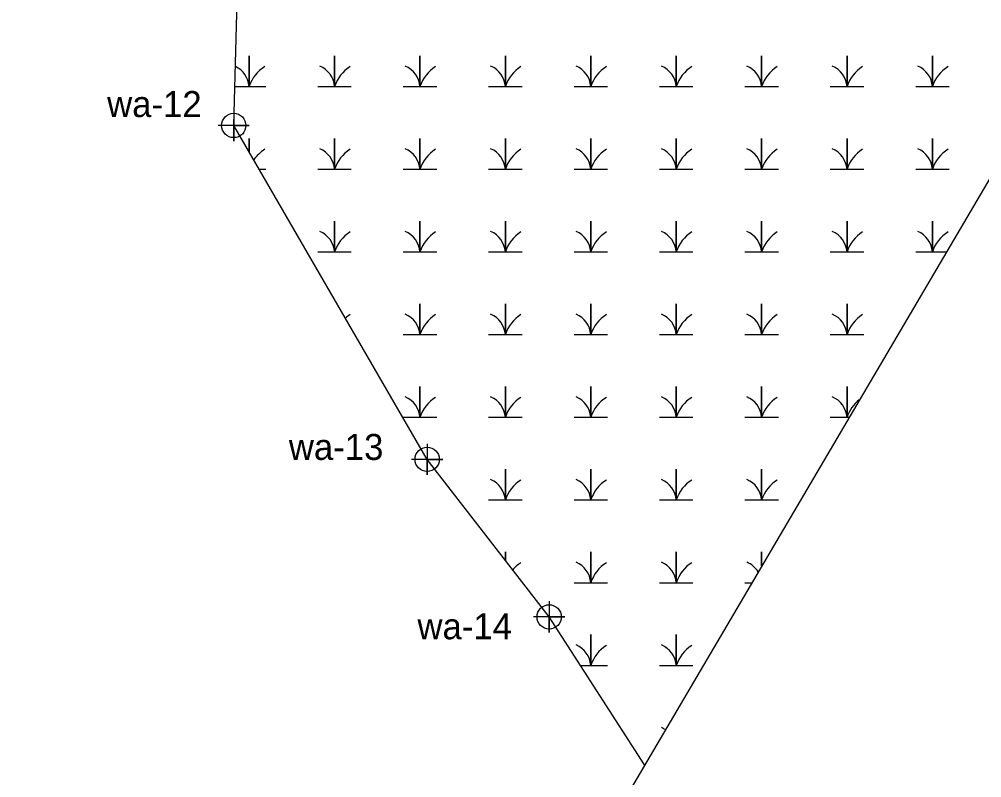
# Model space of a CAD drawing. Extents: x 2379288 to 2381905, y 330670 to 333511.
# Drawn here: x 2379849.1 to 2380034.5, y 331240.1 to 331386.1 of the extents above; entities that cross this region are included whole.
import ezdxf

# ---------------------------------------------------------------- set-up
doc = ezdxf.new("R2010")
doc.units = 0
for name, color, linetype in [('Default', 7, 'Continuous'), ('Exist Environmental Wetland Boundary', 7, 'Continuous'), ('Exist Environmental Wetland Boundary Cogo Number', 7, 'Continuous'), ('Exist Environmental Wetland Boundary Cogo Point CELL', 7, 'Continuous'), ('Exist Hydro Swamp or Marsh', 7, 'Continuous')]:
    doc.layers.add(name, color=color, linetype=linetype)

msp = doc.modelspace()

# ---------------------------------------------------------------- linework, layer by layer
at = {"layer": 'Default'}
msp.add_lwpolyline([(2380453.94, 332065.55), (2379632.78, 330670.47), (2379288.07, 330873.37), (2380109.3, 332268.58)], dxfattribs=at)
at = {"layer": 'Exist Environmental Wetland Boundary'}
msp.add_lwpolyline([(2379969.53, 331242.58), (2379951.18, 331271.07), (2379927.68, 331301.39), (2379890.44, 331365.66), (2379892.64, 331447.19), (2379906.39, 331470.26), (2379921.41, 331493.05), (2379928.27, 331503.45), (2379949.79, 331537.93), (2379979.44, 331586.24), (2380001.81, 331628.04), (2380020.7, 331661.36), (2380049.79, 331711.02), (2380074.34, 331755.11), (2380080.4, 331764.13), (2380105.64, 331802.62), (2380125.36, 331845.41), (2380131.51, 331853.8), (2380135.55, 331859.31), (2380151.44, 331880.98), (2380179.52, 331921.73), (2380190.43, 331937.74), (2380215.91, 331979.8)], dxfattribs=at)
at = {"layer": 'Exist Environmental Wetland Boundary Cogo Point CELL'}
for points in [[(2379890.43, 331368.66), (2379890.43, 331362.66), (2379890.43, 331365.66), (2379893.43, 331365.66), (2379887.43, 331365.66)], [(2379927.68, 331304.39), (2379927.68, 331298.39), (2379927.68, 331301.39), (2379930.68, 331301.39), (2379924.68, 331301.39)], [(2379951.18, 331274.07), (2379951.18, 331268.07), (2379951.18, 331271.07), (2379954.18, 331271.07), (2379948.18, 331271.07)]]:
    msp.add_lwpolyline(points, dxfattribs=at)
for centre in [(2379890.43, 331365.66), (2379927.68, 331301.39), (2379951.18, 331271.07)]:
    msp.add_circle(centre, 2.34, dxfattribs=at)
at = {"layer": 'Exist Hydro Swamp or Marsh'}
for p, q in [((2379895.32, 331357.24), (2379896.62, 331357.24)), ((2379988.87, 331277.65), (2379990.18, 331277.65))]:
    msp.add_line(p, q, dxfattribs=at)
for points in [[(2379890.64, 331373.16), (2379893.39, 331373.16), (2379893.39, 331379.08), (2379893.39, 331373.16), (2379896.62, 331373.16)], [(2379906.62, 331373.16), (2379909.84, 331373.16), (2379909.84, 331379.08), (2379909.84, 331373.16), (2379913.07, 331373.16)], [(2379923.07, 331373.16), (2379926.29, 331373.16), (2379926.29, 331379.08), (2379926.29, 331373.16), (2379929.52, 331373.16)], [(2379939.52, 331373.16), (2379942.75, 331373.16), (2379942.75, 331379.08), (2379942.75, 331373.16), (2379945.97, 331373.16)], [(2379955.97, 331373.16), (2379959.2, 331373.16), (2379959.2, 331379.08), (2379959.2, 331373.16), (2379962.42, 331373.16)], [(2379972.42, 331373.16), (2379975.65, 331373.16), (2379975.65, 331379.08), (2379975.65, 331373.16), (2379978.87, 331373.16)], [(2379988.87, 331373.16), (2379992.1, 331373.16), (2379992.1, 331379.08), (2379992.1, 331373.16), (2379995.32, 331373.16)], [(2380005.32, 331373.16), (2380008.55, 331373.16), (2380008.55, 331379.08), (2380008.55, 331373.16), (2380011.78, 331373.16)], [(2380021.78, 331373.16), (2380025, 331373.16), (2380025, 331379.08), (2380025, 331373.16), (2380028.23, 331373.16)], [(2379893.39, 331360.56), (2379893.39, 331363.16), (2379893.39, 331360.56)], [(2379906.62, 331357.24), (2379909.84, 331357.24), (2379909.84, 331363.16), (2379909.84, 331357.24), (2379913.07, 331357.24)], [(2379923.07, 331357.24), (2379926.29, 331357.24), (2379926.29, 331363.16), (2379926.29, 331357.24), (2379929.52, 331357.24)], [(2379939.52, 331357.24), (2379942.75, 331357.24), (2379942.75, 331363.16), (2379942.75, 331357.24), (2379945.97, 331357.24)], [(2379955.97, 331357.24), (2379959.2, 331357.24), (2379959.2, 331363.16), (2379959.2, 331357.24), (2379962.42, 331357.24)], [(2379972.42, 331357.24), (2379975.65, 331357.24), (2379975.65, 331363.16), (2379975.65, 331357.24), (2379978.87, 331357.24)], [(2379988.87, 331357.24), (2379992.1, 331357.24), (2379992.1, 331363.16), (2379992.1, 331357.24), (2379995.32, 331357.24)], [(2380005.32, 331357.24), (2380008.55, 331357.24), (2380008.55, 331363.16), (2380008.55, 331357.24), (2380011.78, 331357.24)], [(2380021.78, 331357.24), (2380025, 331357.24), (2380025, 331363.16), (2380025, 331357.24), (2380028.23, 331357.24)], [(2379906.62, 331341.33), (2379909.84, 331341.33), (2379909.84, 331347.24), (2379909.84, 331341.33), (2379913.07, 331341.33)], [(2379923.07, 331341.33), (2379926.29, 331341.33), (2379926.29, 331347.24), (2379926.29, 331341.33), (2379929.52, 331341.33)], [(2379939.52, 331341.33), (2379942.75, 331341.33), (2379942.75, 331347.24), (2379942.75, 331341.33), (2379945.97, 331341.33)], [(2379955.97, 331341.33), (2379959.2, 331341.33), (2379959.2, 331347.24), (2379959.2, 331341.33), (2379962.42, 331341.33)], [(2379972.42, 331341.33), (2379975.65, 331341.33), (2379975.65, 331347.24), (2379975.65, 331341.33), (2379978.87, 331341.33)], [(2379988.87, 331341.33), (2379992.1, 331341.33), (2379992.1, 331347.24), (2379992.1, 331341.33), (2379995.32, 331341.33)], [(2380005.32, 331341.33), (2380008.55, 331341.33), (2380008.55, 331347.24), (2380008.55, 331341.33), (2380011.78, 331341.33)], [(2380021.78, 331341.33), (2380025, 331341.33), (2380025, 331347.24), (2380025, 331341.33), (2380027.66, 331341.33)], [(2379923.07, 331325.41), (2379926.29, 331325.41), (2379926.29, 331331.33), (2379926.29, 331325.41), (2379929.52, 331325.41)], [(2379939.52, 331325.41), (2379942.75, 331325.41), (2379942.75, 331331.33), (2379942.75, 331325.41), (2379945.97, 331325.41)], [(2379955.97, 331325.41), (2379959.2, 331325.41), (2379959.2, 331331.33), (2379959.2, 331325.41), (2379962.42, 331325.41)], [(2379972.42, 331325.41), (2379975.65, 331325.41), (2379975.65, 331331.33), (2379975.65, 331325.41), (2379978.87, 331325.41)], [(2379988.87, 331325.41), (2379992.1, 331325.41), (2379992.1, 331331.33), (2379992.1, 331325.41), (2379995.32, 331325.41)], [(2380005.32, 331325.41), (2380008.55, 331325.41), (2380008.55, 331331.33), (2380008.55, 331325.41), (2380011.78, 331325.41)], [(2379923.07, 331309.49), (2379926.29, 331309.49), (2379926.29, 331315.41), (2379926.29, 331309.49), (2379929.52, 331309.49)], [(2379939.52, 331309.49), (2379942.75, 331309.49), (2379942.75, 331315.41), (2379942.75, 331309.49), (2379945.97, 331309.49)], [(2379955.97, 331309.49), (2379959.2, 331309.49), (2379959.2, 331315.41), (2379959.2, 331309.49), (2379962.42, 331309.49)], [(2379972.42, 331309.49), (2379975.65, 331309.49), (2379975.65, 331315.41), (2379975.65, 331309.49), (2379978.87, 331309.49)], [(2379988.87, 331309.49), (2379992.1, 331309.49), (2379992.1, 331315.41), (2379992.1, 331309.49), (2379995.32, 331309.49)], [(2380005.32, 331309.49), (2380008.55, 331309.49), (2380008.55, 331315.41), (2380008.55, 331309.49), (2380008.92, 331309.49)], [(2379939.52, 331293.57), (2379942.75, 331293.57), (2379942.75, 331299.49), (2379942.75, 331293.57), (2379945.97, 331293.57)], [(2379955.97, 331293.57), (2379959.2, 331293.57), (2379959.2, 331299.49), (2379959.2, 331293.57), (2379962.42, 331293.57)], [(2379972.42, 331293.57), (2379975.65, 331293.57), (2379975.65, 331299.49), (2379975.65, 331293.57), (2379978.87, 331293.57)], [(2379988.87, 331293.57), (2379992.1, 331293.57), (2379992.1, 331299.49), (2379992.1, 331293.57), (2379995.32, 331293.57)], [(2379942.75, 331281.95), (2379942.75, 331283.57), (2379942.75, 331281.95)], [(2379955.97, 331277.65), (2379959.2, 331277.65), (2379959.2, 331283.57), (2379959.2, 331277.65), (2379962.42, 331277.65)], [(2379972.42, 331277.65), (2379975.65, 331277.65), (2379975.65, 331283.57), (2379975.65, 331277.65), (2379978.87, 331277.65)], [(2379992.1, 331280.92), (2379992.1, 331283.57), (2379992.1, 331280.92)], [(2379957.19, 331261.74), (2379959.2, 331261.74), (2379959.2, 331267.65), (2379959.2, 331261.74), (2379962.42, 331261.74)], [(2379972.42, 331261.74), (2379975.65, 331261.74), (2379975.65, 331267.65), (2379975.65, 331261.74), (2379978.87, 331261.74)]]:
    msp.add_lwpolyline(points, dxfattribs=at)
for centre, radius, start, end in [((2379888.79, 331372.83), 4.61, 4.1403, 64.9754), ((2379900.23, 331370.89), 7.21, 122.1274, 161.6222), ((2379905.24, 331372.83), 4.61, 4.1403, 67.535), ((2379916.68, 331370.89), 7.21, 122.1274, 161.6222), ((2379921.69, 331372.83), 4.61, 4.1403, 67.535), ((2379933.14, 331370.89), 7.21, 122.1274, 161.6222), ((2379938.15, 331372.83), 4.61, 4.1403, 67.535), ((2379949.59, 331370.89), 7.21, 122.1274, 161.6222), ((2379954.6, 331372.83), 4.61, 4.1403, 67.535), ((2379966.04, 331370.89), 7.21, 122.1274, 161.6222), ((2379971.05, 331372.83), 4.61, 4.1403, 67.535), ((2379982.49, 331370.89), 7.21, 122.1274, 161.6222), ((2379987.5, 331372.83), 4.61, 4.1403, 67.535), ((2379998.94, 331370.89), 7.21, 122.1274, 161.6222), ((2380003.95, 331372.83), 4.61, 4.1403, 67.535), ((2380015.39, 331370.89), 7.21, 122.1274, 161.6222), ((2380020.4, 331372.83), 4.61, 4.1403, 67.535), ((2380031.84, 331370.89), 7.21, 122.1274, 161.6222), ((2379900.23, 331354.97), 7.21, 122.1274, 145.6981), ((2379905.24, 331356.91), 4.61, 4.1403, 67.535), ((2379916.68, 331354.97), 7.21, 122.1274, 161.6222), ((2379921.69, 331356.91), 4.61, 4.1403, 67.535), ((2379933.14, 331354.97), 7.21, 122.1274, 161.6222), ((2379938.15, 331356.91), 4.61, 4.1403, 67.535), ((2379949.59, 331354.97), 7.21, 122.1274, 161.6222), ((2379954.6, 331356.91), 4.61, 4.1403, 67.535), ((2379966.04, 331354.97), 7.21, 122.1274, 161.6222), ((2379971.05, 331356.91), 4.61, 4.1403, 67.535), ((2379982.49, 331354.97), 7.21, 122.1274, 161.6222), ((2379987.5, 331356.91), 4.61, 4.1403, 67.535), ((2379998.94, 331354.97), 7.21, 122.1274, 161.6222), ((2380003.95, 331356.91), 4.61, 4.1403, 67.535), ((2380015.39, 331354.97), 7.21, 122.1274, 161.6222), ((2380020.4, 331356.91), 4.61, 4.1403, 67.535), ((2380031.84, 331354.97), 7.21, 122.1274, 161.6222), ((2379905.24, 331340.99), 4.61, 4.1403, 67.535), ((2379916.68, 331339.05), 7.21, 122.1274, 161.6222), ((2379921.69, 331340.99), 4.61, 4.1403, 67.535), ((2379933.14, 331339.05), 7.21, 122.1274, 161.6222), ((2379938.15, 331340.99), 4.61, 4.1403, 67.535), ((2379949.59, 331339.05), 7.21, 122.1274, 161.6222), ((2379954.6, 331340.99), 4.61, 4.1403, 67.535), ((2379966.04, 331339.05), 7.21, 122.1274, 161.6222), ((2379971.05, 331340.99), 4.61, 4.1403, 67.535), ((2379982.49, 331339.05), 7.21, 122.1274, 161.6222), ((2379987.5, 331340.99), 4.61, 4.1403, 67.535), ((2379998.94, 331339.05), 7.21, 122.1274, 161.6222), ((2380003.95, 331340.99), 4.61, 4.1403, 67.535), ((2380015.39, 331339.05), 7.21, 122.1274, 161.6222), ((2380020.4, 331340.99), 4.61, 4.1403, 67.535), ((2380031.84, 331339.05), 7.21, 122.1274, 161.6222), ((2379916.68, 331323.14), 7.21, 122.1274, 131.1938), ((2379921.69, 331325.07), 4.61, 4.1403, 67.535), ((2379933.14, 331323.14), 7.21, 122.1274, 161.6222), ((2379938.15, 331325.07), 4.61, 4.1403, 67.535), ((2379949.59, 331323.14), 7.21, 122.1274, 161.6222), ((2379954.6, 331325.07), 4.61, 4.1403, 67.535), ((2379966.04, 331323.14), 7.21, 122.1274, 161.6222), ((2379971.05, 331325.07), 4.61, 4.1403, 67.535), ((2379982.49, 331323.14), 7.21, 122.1274, 161.6222), ((2379987.5, 331325.07), 4.61, 4.1403, 67.535), ((2379998.94, 331323.14), 7.21, 122.1274, 161.6222), ((2380003.95, 331325.07), 4.61, 4.1403, 67.535), ((2380015.39, 331323.14), 7.21, 122.1274, 161.6222), ((2379921.69, 331309.16), 4.61, 4.1403, 67.535), ((2379933.14, 331307.22), 7.21, 122.1274, 161.6222), ((2379938.15, 331309.16), 4.61, 4.1403, 67.535), ((2379949.59, 331307.22), 7.21, 122.1274, 161.6222), ((2379954.6, 331309.16), 4.61, 4.1403, 67.535), ((2379966.04, 331307.22), 7.21, 122.1274, 161.6222), ((2379971.05, 331309.16), 4.61, 4.1403, 67.535), ((2379982.49, 331307.22), 7.21, 122.1274, 161.6222), ((2379987.5, 331309.16), 4.61, 4.1403, 67.535), ((2379998.94, 331307.22), 7.21, 122.1274, 161.6222), ((2380003.95, 331309.16), 4.61, 4.1403, 67.535), ((2380015.39, 331307.22), 7.21, 128.5561, 161.6222), ((2379938.15, 331293.24), 4.61, 4.1403, 67.535), ((2379949.59, 331291.3), 7.21, 122.1274, 161.6222), ((2379954.6, 331293.24), 4.61, 4.1403, 67.535), ((2379966.04, 331291.3), 7.21, 122.1274, 161.6222), ((2379971.05, 331293.24), 4.61, 4.1403, 67.535), ((2379982.49, 331291.3), 7.21, 122.1274, 161.6222), ((2379987.5, 331293.24), 4.61, 4.1403, 67.535), ((2379998.94, 331291.3), 7.21, 122.1274, 161.6222), ((2379949.59, 331275.38), 7.21, 122.1274, 138.8478), ((2379954.6, 331277.32), 4.61, 4.1403, 67.535), ((2379966.04, 331275.38), 7.21, 122.1274, 161.6222), ((2379971.05, 331277.32), 4.61, 4.1403, 67.535), ((2379982.49, 331275.38), 7.21, 122.1274, 161.6222), ((2379987.5, 331277.32), 4.61, 31.8595, 67.535), ((2379954.6, 331261.4), 4.61, 4.1403, 67.535), ((2379966.04, 331259.46), 7.21, 122.1274, 161.6222), ((2379971.05, 331261.4), 4.61, 4.1403, 67.535), ((2379982.49, 331259.46), 7.21, 122.1274, 161.6222), ((2379971.05, 331245.49), 4.61, 57.4099, 67.535)]:
    msp.add_arc(centre, radius, start, end, dxfattribs=at)

# ---------------------------------------------------------------- texts
at = {"layer": 'Exist Environmental Wetland Boundary Cogo Number'}
for s, p in [('wa-12', (2379866.04, 331367.28)), ('wa-13', (2379901.04, 331301.28)), ('wa-14', (2379925.81, 331266.76))]:
    msp.add_text(s, height=5, dxfattribs=at).set_placement(p)

doc.saveas('drawing.dxf')
